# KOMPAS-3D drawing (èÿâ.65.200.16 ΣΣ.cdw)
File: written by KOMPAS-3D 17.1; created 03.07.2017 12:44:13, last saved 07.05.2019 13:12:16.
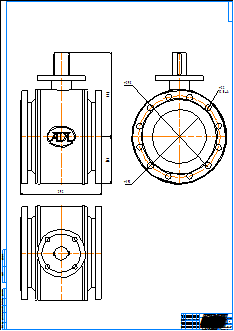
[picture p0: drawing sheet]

Sheet 1: A0, portrait

Title block, sheet 1: name: КШГ.65.200.16 фф; material: Внимание! Данный продукт является объектом авторского права ООО «Торговый Дом АДЛ». / Запрещается изменение, копирование, распространение / (в том числе путем копирования на другие сайты и ресурсы в Интернете) / или любое иное использование информации и объектов без предварительного / согласия правообладателя (ООО «Торговый Дом АДЛ»).; sheets: 1; organisation: ООО "Торговый дом АДЛ"; sheet format: A0; stored path: C:\Users\kka\KOMPAS_Work\!Trash\СС02 СС03 ФФ Смотровые стекла\СС01.cdw

Views: Спереди 1, Проекционный вид 2, Проекционный вид 3
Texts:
  Klimkovich
  ADL
Dimensions and other numbers on the sheet: 304; 292; 168; 295; 195; 22; 12 Отв.; 1:1; 1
